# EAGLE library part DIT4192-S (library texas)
192kHz Digital Audio Transmitter Software Mode Source: http://focus.ti.com/lit/ds/symlink/dit4192.pdf
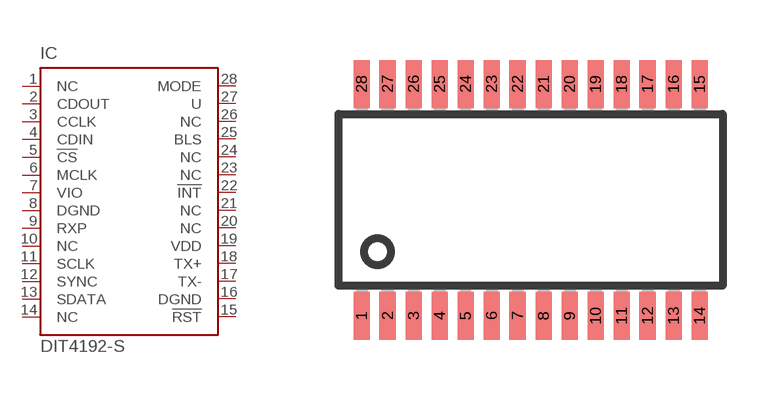
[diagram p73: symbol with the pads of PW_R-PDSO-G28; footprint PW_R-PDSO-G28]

Designator prefix IC

## DIT4192-S (MF: TEXAS INSTRUMENTS; MPN: DIT4192IPW; OC_FARNELL: 7455057; OC_NEWARK: 74C9511)  [PW_R-PDSO-G28]
1  NC  nc
2  CDOUT  out
3  CCLK  in
4  CDIN  in
5  !CS  in
6  MCLK  in
7  VIO  pwr
8  DGND  pwr
9  RXP  in
10  NC  nc
11  SCLK
12  SYNC
13  SDATA  in
14  NC  nc
15  !RST  in
16  DGND  pwr
17  TX-  out
18  TX+  out
19  VDD  pwr
20  NC  nc
21  NC  nc
22  !INT  oc
23  NC  nc
24  NC  nc
25  BLS
26  NC  nc
27  U  in
28  MODE  in

## Footprint PW_R-PDSO-G28 (pad centres in mm)
PLASTIC SMALL-OUTLINE PACKAGE SO 28 JEDEC MO-153, PW Type Source: www.ti.com/.. slvs087l.pdf
smd 0.4 x 1.2: 1 -4.225,-2.9; 2 -3.575,-2.9; 3 -2.925,-2.9; 4 -2.275,-2.9; 5 -1.625,-2.9; 6 -0.975,-2.9; 7 -0.325,-2.9; 8 0.325,-2.9; 9 0.975,-2.9; 10 1.625,-2.9; 11 2.275,-2.9; 12 2.925,-2.9; 13 3.575,-2.9; 14 4.225,-2.9; 15 4.225,2.9; 16 3.575,2.9; 17 2.925,2.9; 18 2.275,2.9; 19 1.625,2.9; 20 0.975,2.9; 21 0.325,2.9; 22 -0.325,2.9; 23 -0.975,2.9; 24 -1.625,2.9; 25 -2.275,2.9; 26 -2.925,2.9; 27 -3.575,2.9; 28 -4.225,2.9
